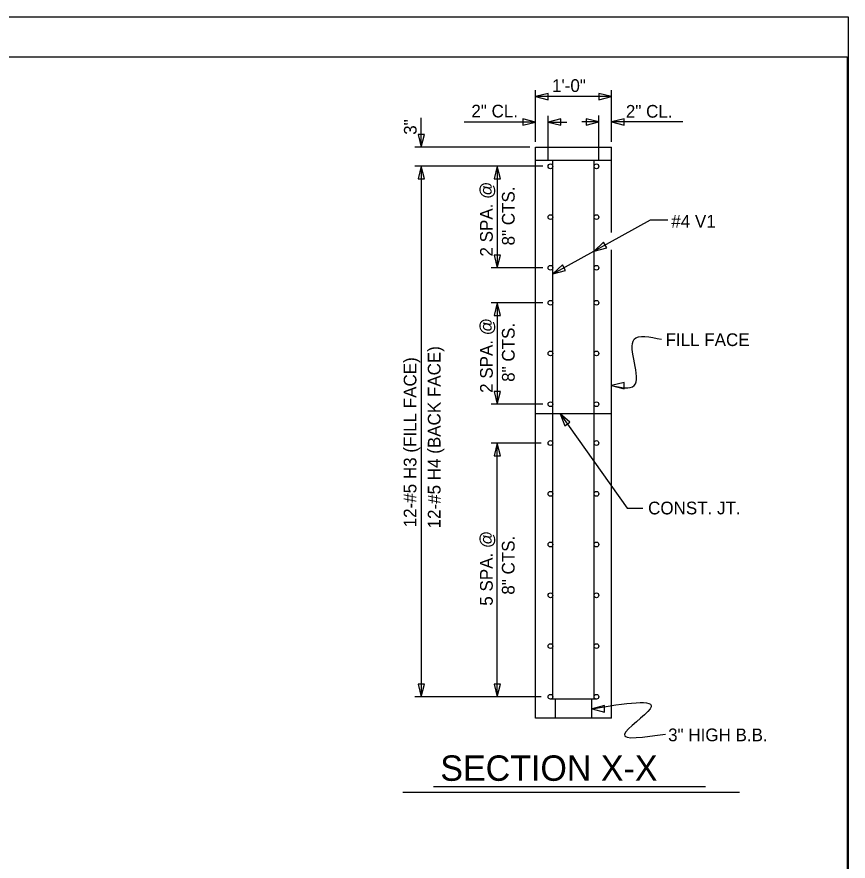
# Model space of a CAD drawing. Extents: x -41 to 191, y -168 to 6.
# Drawn here: x 33.05 to 43.97, y -80.65 to -69.56 of the extents above; entities that cross this region are included whole.
import ezdxf

# ---------------------------------------------------------------- set-up
doc = ezdxf.new("R2010")
doc.units = 0
for name, color, linetype in [('Arrowhead Terminators CELL', 7, 'Continuous'), ('Dimension Lines', 7, 'Continuous'), ('Mis Object Lines', 7, 'Continuous'), ('Mis Object Lines Hidden', 7, 'Continuous'), ('Plan Sheet CELL', 7, 'Continuous'), ('Plot Shape CELL', 7, 'Continuous'), ('Rebar Lines', 7, 'Continuous'), ('Text', 7, 'Continuous'), ('Title Text', 7, 'Continuous'), ('User Information Notes CELL', 7, 'Continuous')]:
    doc.layers.add(name, color=color, linetype=linetype)

msp = doc.modelspace()

# ---------------------------------------------------------------- linework, layer by layer
at = {"layer": 'Arrowhead Terminators CELL'}
for points in [[(39.865, -70.609), (40.031, -70.651), (40.031, -70.568)], [(40.865, -70.609), (40.699, -70.568), (40.699, -70.651)], [(39.865, -70.944), (39.699, -70.902), (39.699, -70.985)], [(40.032, -70.944), (40.198, -70.985), (40.198, -70.902)], [(40.699, -70.943), (40.532, -70.901), (40.532, -70.984)], [(40.865, -70.943), (41.031, -70.984), (41.031, -70.901)], [(38.365, -71.276), (38.407, -71.11), (38.324, -71.11)], [(38.365, -71.526), (38.324, -71.692), (38.407, -71.692)], [(39.365, -71.526), (39.324, -71.692), (39.407, -71.692)], [(40.636, -72.641), (40.802, -72.597), (40.762, -72.524)], [(39.365, -72.859), (39.407, -72.693), (39.324, -72.693)], [(40.095, -72.939), (40.26, -72.895), (40.22, -72.822)], [(39.365, -73.318), (39.324, -73.484), (39.407, -73.484)], [(40.865, -74.407), (41.031, -74.449), (41.031, -74.366)], [(39.365, -74.651), (39.407, -74.485), (39.324, -74.485)], [(40.189, -74.776), (40.251, -74.935), (40.319, -74.887)], [(39.365, -75.161), (39.324, -75.327), (39.407, -75.327)], [(38.365, -78.494), (38.407, -78.328), (38.324, -78.328)], [(39.365, -78.494), (39.407, -78.328), (39.324, -78.328)], [(40.609, -78.652), (40.775, -78.694), (40.775, -78.61)]]:
    msp.add_lwpolyline(points, close=True, dxfattribs=at)
at = {"layer": 'Dimension Lines'}
for p, q in [((39.865, -71.204), (39.865, -70.526)), ((40.865, -71.204), (40.865, -70.526)), ((40.865, -70.609), (39.865, -70.609)), ((40.032, -71.454), (40.032, -70.861)), ((40.699, -71.454), (40.699, -70.859)), ((38.365, -71.276), (38.365, -70.888)), ((39.865, -70.944), (38.928, -70.944)), ((40.032, -70.944), (40.278, -70.944)), ((40.699, -70.943), (40.476, -70.943)), ((41.802, -70.943), (40.865, -70.943)), ((39.793, -71.276), (38.282, -71.276)), ((39.961, -71.526), (38.282, -71.526)), ((38.365, -71.526), (38.365, -78.494)), ((39.365, -71.526), (39.365, -72.859)), ((40.095, -72.939), (41.379, -72.231)), ((41.379, -72.231), (41.605, -72.231)), ((39.961, -72.859), (39.282, -72.859)), ((39.961, -73.318), (39.282, -73.318)), ((39.365, -73.318), (39.365, -74.651)), ((39.961, -74.651), (39.282, -74.651)), ((40.189, -74.776), (41.071, -76.016)), ((39.941, -75.161), (39.282, -75.161)), ((39.365, -78.494), (39.365, -75.161)), ((41.071, -76.016), (41.275, -76.016)), ((39.941, -78.494), (38.282, -78.494))]:
    msp.add_line(p, q, dxfattribs=at)
for points in [[(40.865, -74.407), (41.162, -74.407), (41.162, -73.798), (41.521, -73.798)], [(40.609, -78.652), (41.375, -78.652), (41.036, -78.984), (41.573, -78.984)]]:
    msp.add_spline(points, degree=3, dxfattribs=at)
at = {"layer": 'Mis Object Lines'}
for p, q in [((39.865, -78.776), (39.865, -71.276)), ((39.865, -71.276), (40.865, -71.276)), ((40.865, -72.397), (40.865, -71.276)), ((40.865, -78.776), (40.865, -72.623)), ((40.865, -78.776), (39.865, -78.776))]:
    msp.add_line(p, q, dxfattribs=at)
at = {"layer": 'Mis Object Lines Hidden'}
msp.add_line((40.865, -74.776), (39.865, -74.776), dxfattribs=at)
at = {"layer": 'Plan Sheet CELL'}
for p, q in [((43.974, -69.563), (43.974, -69.563)), ((1.402, -70.087), (43.962, -70.087)), ((43.962, -70.087), (43.962, -98.017))]:
    msp.add_line(p, q, dxfattribs=at)
at = {"layer": 'Plot Shape CELL'}
msp.add_lwpolyline([(0, -69.563), (43.974, -69.563), (43.974, -98.823), (0, -98.823)], close=True, dxfattribs=at)
at = {"layer": 'Rebar Lines'}
for p, q in [((40.095, -78.526), (40.095, -71.443)), ((40.636, -78.526), (40.636, -71.443)), ((40.667, -78.526), (40.063, -78.526)), ((40.127, -78.526), (40.127, -78.776)), ((40.602, -78.526), (40.602, -78.776))]:
    msp.add_line(p, q, dxfattribs=at)
for centre in [(40.063, -71.526), (40.667, -71.526), (40.063, -72.193), (40.667, -72.193), (40.063, -72.859), (40.667, -72.859), (40.063, -73.318), (40.667, -73.318), (40.063, -73.984), (40.667, -73.984), (40.063, -74.651), (40.667, -74.651), (40.063, -75.161), (40.667, -75.161), (40.063, -75.828), (40.667, -75.828), (40.063, -76.494), (40.667, -76.494), (40.063, -77.161), (40.667, -77.161), (40.063, -77.828), (40.667, -77.828), (40.063, -78.494), (40.667, -78.494)]:
    msp.add_ellipse(centre, major_axis=(0, -0.0313), ratio=0.99999, dxfattribs=at)
at = {"layer": 'Title Text'}
for p, q in [((38.526, -79.674), (42.1, -79.674)), ((38.123, -79.747), (42.545, -79.747))]:
    msp.add_line(p, q, dxfattribs=at)
at = {"layer": 'User Information Notes CELL'}
msp.add_line((39.865, -71.443), (40.865, -71.443), dxfattribs=at)

# ---------------------------------------------------------------- texts
at = {"layer": 'Text'}
for s, rotation, p in [('1\'-0"', 360, (40.084, -70.549)), ('2" CL.', 360, (39.024, -70.884)), ('2" CL.', 360, (41.054, -70.887)), ('3"', 90, (38.305, -71.112)), ('2 SPA. @', 90, (39.305, -72.711)), ('8" CTS.', 90, (39.593, -72.565)), ('#4 V1', 360, (41.651, -72.331)), ('2 SPA. @', 90, (39.305, -74.502)), ('8" CTS.', 90, (39.593, -74.357)), ('FILL FACE', 360, (41.575, -73.887)), ('12-#5 H4 (BACK FACE)', 90, (38.619, -76.283)), ('12-#5 H3 (FILL FACE)', 90, (38.302, -76.268)), ('CONST. JT.', 360, (41.346, -76.098)), ('5 SPA. @', 90, (39.305, -77.298)), ('8" CTS.', 90, (39.592, -77.153))]:
    msp.add_text(s, height=0.167, rotation=rotation, dxfattribs=at).set_placement(p)
msp.add_text('3" HIGH B.B.', height=0.167, dxfattribs=at).set_placement((41.609, -79.078))
at = {"layer": 'Title Text'}
msp.add_text('SECTION X-X', height=0.33399, dxfattribs=at).set_placement((38.616, -79.598))

doc.saveas('drawing.dxf')
